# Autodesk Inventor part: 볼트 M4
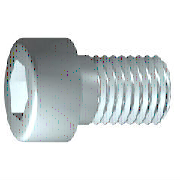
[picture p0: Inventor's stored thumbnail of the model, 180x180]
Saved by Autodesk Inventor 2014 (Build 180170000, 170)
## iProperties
IsCustomPart: 0
Created: 2012-02
Part Number: 볼트 M4
Material: 스테인리스강
Description: 6각 소켓 머리 캡 나사
Document SubType Name: Modeling
Standard: ISO 4762
Designer: mduedu
Standard Revision: Fourth edition 2004-03-01
Standards Organization: ISO
Language: ko-KR
Size Designation: M4 x 12
Categories: <MemberInstance><Categories><Category DisplayName="조임쇠" InternalName="e4da775c-781d-43d5-af7c-5136215cf5a6" Mnemonic="FSTN"><Category DisplayName="볼트" InternalN
Density: 7.75 g/cm^3
Appearance: 반광택
Author: mduedu
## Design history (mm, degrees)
sketch "스케치1"
  geometry: L1 (-1, 0)-(12, 0); L2 (12, 0)-(12, 2); L3 (12, 2)-(1.75, 2); L4 (1.75, 2)-(1.32, 2); L5 (1.32, 2)-(0, 2); L6 (0, 2)-(0, 3.5); L7 (0, 3.5)-(-4, 3.5); L8 (-4, 3.5)-(-4, 1.732); L9 (-4, 1.732)-(-2, 1.732); L10 (-2, 1.732)-(-1, 0); L11 (-7.2, 0)-(15.2, 0) reference; L12 (0, -0.7)-(0, 4.2) reference; L13 (1.75, 2)-(0, 2)
  constraints: 22 end point, 6 parallel, 2 collinear, 2 perpendicular, 1 horizontal, 1 point on line
  dimensions: "d1" = 10.25 distance from line of L3.end L2 (= GEL); "d2" = 0.42952 distance of L4.end L3.end (computed from GAL); "d3" = 4 distance between parallel lines of L8 L6 (= KOH); "d4" = 2 distance of L8.end L9.end (= INTI); "d5" = 60 deg angle of L10 L1; "d6" = 4 diameter of L3 L1 (= GD); "d7" = 4 diameter of L5 L1 (= BDM); "d8" = 3.4641 diameter of L9 L1 (= 1.1547 x SW); "d9" = 7 diameter of L7 L1 (= KOD); "d26" = 12 distance between parallel lines of L12 L2 (= NLG)
revolve "본체" sketch "스케치1" stored, may be unused: angle "d10" = 90 deg
sketch "스케치2"
  geometry: L1 (0, -4.9)-(0, 4.9) reference; L2 (-4.9, 0)-(4.9, 0) reference; L3 (1.732, 0)-(0.866, -1.5); L4 (0.866, -1.5)-(-0.866, -1.5); L5 (-0.866, -1.5)-(-1.732, 0); L6 (-1.732, 0)-(-0.866, 1.5); L7 (-0.866, 1.5)-(0.866, 1.5); L8 (0.866, 1.5)-(1.732, 0); 2 further points
  constraints: 12 end point, 1 coincident, 1 horizontal alignment, 1 point on line, 12 other
extrude "슬롯" join sketch "스케치2" stored distance "d11" = 10; taper "d12" = 0 deg
workplane "Work Plane1"
fillet "Fillet2" dims "d30" = 0.1 (= R)
body "Solid1"
fillet "모깎기1" dims "d17" = 0.4 (= RR)
feature "스레드" dims "d13" = 10.25 (= GEL), "d14" = 0
chamfer "모따기1" distance "d15" = 0.42941 (= -0.5 x SPD + 0.5 x GD); stored, may be unused: second distance "d16" = 0.42941 (= GUL), angle "d27" = 45 deg
other parameters: "GD" = 4 [user parameter; used in 2 equation terms], "NLG" = 12 [user parameter; used in 1 equation term], "GEL" = 10.25 [user parameter; used in 2 equation terms], "KOD" = 7 [user parameter; used in 1 equation term], "KOH" = 4 [user parameter; used in 1 equation term], "INTI" = 2 [user parameter; used in 1 equation term], "GAL" = 0.42941 (= 0.61345 x PTC) [user parameter; used in 1 equation term], "GUL" = 0.42941 (= 0.61345 x PTC) [user parameter; used in 1 equation term], "BDM" = 4 (= NND) [user parameter; used in 1 equation term], "SW" = 3 [user parameter; used in 2 equation terms], "RR" = 0.4 [user parameter; used in 1 equation term], "SPD" = 3.14117 (= NND - 1.2269 x PTC) [user parameter; used in 1 equation term], "d19" = 0, "d28" = 0, "d29" = 0, "R" = 0.1 [user parameter; used in 1 equation term], "TOA" = 30 deg [user parameter], "GD1" = 3.14117 (= THREADDIA - 1.2269 x PTC) [user parameter], "THREADDIA" = 4 [user parameter; used in 1 equation term], "FAWI" = 45 deg [user parameter], "TPU" = 14.28571 (computed from PTC) [user parameter], "PTC" = 0.7 [user parameter; used in 5 equation terms], "NND" = 4 [user parameter; used in 2 equation terms], "E0" = 3.465 (= 1.155 x SW) [user parameter]
